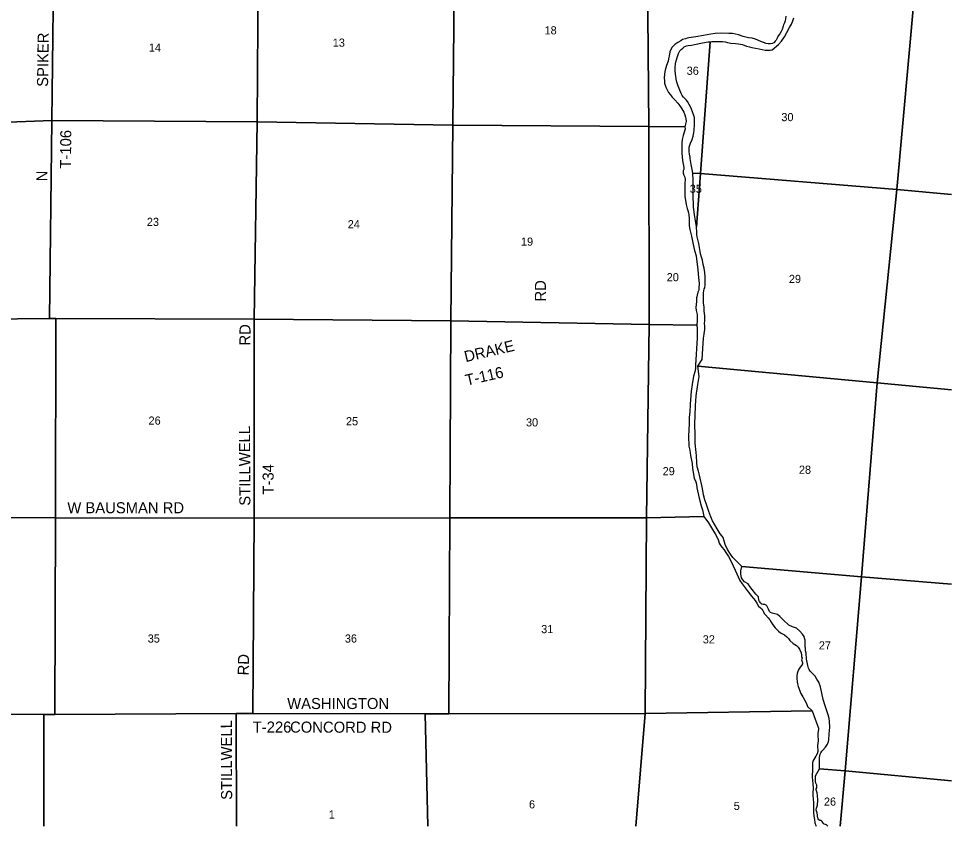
# Model space of a CAD drawing. Extents: x -87 to 2145, y -2128 to 440.
# Drawn here: x 204.7 to 331.2, y -2126.1 to -2016.6 of the extents above; entities that cross this region are included whole.
import ezdxf

# ---------------------------------------------------------------- set-up
doc = ezdxf.new("R2010")
doc.units = 0
for name, color, linetype in [('GM_X_Section', 7, 'Continuous'), ('GM_X_Section_Text', 7, 'Continuous'), ('GM_X_Township_Road_Text', 7, 'Continuous')]:
    doc.layers.add(name, color=color, linetype=linetype)

msp = doc.modelspace()

# ---------------------------------------------------------------- linework, layer by layer
at = {"layer": 'GM_X_Section'}
for points in [[(183.38, -2004.69), (209.52, -2003.86), (209.22, -2030.41), (194.99, -2030.93), (183.1, -2030.7)], [(237.27, -2004.15), (237.06, -2030.59), (209.22, -2030.41), (209.52, -2003.86)], [(237.27, -2004.15), (263.85, -2004.34), (263.59, -2031.02), (237.06, -2030.59)], [(263.85, -2004.34), (288.73, -2004.69), (288.94, -2004.98), (289.06, -2005.09), (289.25, -2005.27), (289.56, -2005.57), (289.96, -2005.92), (290.16, -2031.2), (263.59, -2031.02)], [(298.51, -2019.76), (297.19, -2037.61), (296.15, -2037.56), (296.07, -2037.07), (295.96, -2036.62), (295.94, -2036.39), (295.79, -2035.58), (295.78, -2035.39), (295.69, -2034.99), (295.65, -2034.6), (295.64, -2034.3), (295.66, -2034.04), (295.72, -2033.77), (295.82, -2033.48), (296.06, -2032.98), (296.21, -2032.55), (296.3, -2032.06), (296.33, -2031.74), (296.38, -2030.98), (296.39, -2030.45), (296.36, -2030.03), (296.29, -2029.72), (296.16, -2029.39), (295.9, -2028.73), (295.65, -2028.26), (295.44, -2027.85), (295.24, -2027.59), (294.9, -2027.26), (294.7, -2027.01), (294.57, -2026.73), (294.28, -2026.07), (294.11, -2025.62), (293.99, -2025.19), (293.89, -2024.78), (293.85, -2024.37), (293.78, -2024.18), (293.75, -2023.59), (293.75, -2023.16), (293.78, -2022.71), (293.87, -2022.33), (294.06, -2021.74), (294.1, -2021.6), (294.22, -2021.33), (294.39, -2020.96), (294.56, -2020.78), (294.79, -2020.58), (294.99, -2020.42), (295.29, -2020.28), (295.5, -2020.24), (295.98, -2020.18), (296.38, -2020.11), (297.44, -2019.89), (298.21, -2019.76)], [(183.1, -2030.7), (194.99, -2030.93), (209.22, -2030.41), (208.91, -2057.25), (182.93, -2057.54)], [(209.22, -2030.41), (237.06, -2030.59), (236.68, -2057.34), (209.76, -2057.25), (208.91, -2057.25)], [(237.06, -2030.59), (263.59, -2031.02), (263.35, -2057.57), (236.68, -2057.34)], [(263.59, -2031.02), (290.16, -2031.2), (290.23, -2058.07), (263.35, -2057.57)], [(290.16, -2031.2), (295.07, -2031.26), (295.09, -2031.54), (295.03, -2031.86), (294.85, -2032.44), (294.7, -2032.97), (294.64, -2033.5), (294.66, -2034.08), (294.67, -2034.8), (294.71, -2035.38), (294.74, -2035.8), (294.8, -2036.1), (294.9, -2036.5), (294.93, -2036.81), (294.92, -2037.04), (294.85, -2037.24), (294.83, -2037.37), (294.84, -2037.54), (294.93, -2037.83), (295.07, -2038.11), (295.1, -2038.39), (295.07, -2038.93), (295.08, -2039.81), (295.06, -2040.34), (295.05, -2040.71), (295.15, -2041.23), (295.24, -2041.82), (295.36, -2042.36), (295.47, -2042.63), (295.57, -2042.95), (295.62, -2043.2), (295.63, -2043.7), (295.63, -2044.12), (295.65, -2044.69), (295.75, -2045.18), (295.96, -2046.09), (296.05, -2046.54), (296.17, -2047.23), (296.39, -2048.03), (296.59, -2048.75), (296.65, -2049.22), (296.74, -2049.91), (296.81, -2050.68), (296.92, -2051.7), (296.99, -2052.51), (296.98, -2053.12), (296.94, -2053.4), (296.83, -2053.7), (296.71, -2054.11), (296.67, -2054.32), (296.66, -2054.48), (296.62, -2054.94), (296.57, -2055.76), (296.6, -2056.16), (296.71, -2056.71), (296.72, -2057.51), (296.7, -2058.18), (290.23, -2058.07)], [(297.19, -2037.61), (296.66, -2044.81), (296.43, -2043.47), (296.25, -2042.17), (296.2, -2040.38), (296.2, -2038.51), (296.15, -2037.56)], [(297.19, -2037.61), (323.79, -2039.77), (321.15, -2065.99), (296.8, -2063.72), (297.43, -2062.83), (297.61, -2059.88), (297.61, -2059.88), (297.64, -2059.69), (297.69, -2059.34), (297.77, -2058.74), (297.76, -2058.34), (297.74, -2057.91), (297.75, -2057.64), (297.76, -2056.92), (297.7, -2056.25), (297.68, -2055.71), (297.61, -2055.12), (297.59, -2054.83), (297.57, -2054.67), (297.57, -2054.4), (297.6, -2053.77), (297.69, -2053.26), (297.76, -2053.11), (297.81, -2052.72), (297.82, -2052.25), (297.82, -2051.6), (297.77, -2051.04), (297.67, -2050.42), (297.56, -2049.92), (297.44, -2049.37), (297.31, -2048.93), (297.18, -2048.5), (297.14, -2048.18), (297.04, -2047.65), (296.95, -2047.1), (296.72, -2046.18), (296.69, -2045.86), (296.67, -2045.54), (296.66, -2044.81)], [(208.91, -2057.25), (209.76, -2057.25), (209.72, -2084.32), (182.37, -2084.18), (182.93, -2057.54)], [(209.76, -2057.25), (236.68, -2057.34), (236.68, -2084.35), (209.72, -2084.32)], [(236.68, -2057.34), (263.35, -2057.57), (263.19, -2084.29), (236.68, -2084.35)], [(263.35, -2057.57), (290.23, -2058.07), (289.88, -2084.28), (263.19, -2084.29)], [(290.23, -2058.07), (296.7, -2058.18), (296.71, -2058.65), (296.75, -2059.86), (296.75, -2059.87), (296.5, -2063.6), (296.5, -2063.96), (296.44, -2064.34), (296.23, -2065.09), (296.04, -2066.2), (295.92, -2067.13), (295.78, -2068.86), (295.73, -2069.97), (295.64, -2070.64), (295.63, -2071.51), (295.57, -2073.21), (295.6, -2074.59), (295.72, -2075.13), (295.82, -2075.86), (296.04, -2076.95), (296.12, -2077.63), (296.33, -2078.91), (296.54, -2079.43), (296.64, -2079.74), (296.69, -2080.24), (296.99, -2081.65), (297.26, -2082.66), (297.45, -2083.22), (297.64, -2084.12), (289.88, -2084.28)], [(321.15, -2065.99), (319.03, -2092.32), (302.81, -2090.91), (301.57, -2089.7), (301.23, -2089.21), (300.84, -2088.61), (300.52, -2087.92), (300.25, -2086.97), (300.12, -2086.78), (299.84, -2086.47), (299.43, -2085.79), (298.81, -2084.69), (298.57, -2084.16), (298.3, -2083.44), (297.99, -2082.5), (297.78, -2081.84), (297.61, -2081.17), (297.45, -2080.31), (297.06, -2078.53), (296.93, -2077.96), (296.73, -2077.38), (296.68, -2076.81), (296.64, -2075.88), (296.61, -2075.44), (296.46, -2074.19), (296.46, -2073.14), (296.41, -2071.53), (296.48, -2070.4), (296.52, -2069.09), (296.55, -2068.39), (296.6, -2067.84), (296.64, -2067.36), (296.68, -2067.16), (296.8, -2066.22), (297.01, -2065.12), (296.8, -2063.72)], [(182.37, -2084.18), (209.72, -2084.32), (209.65, -2110.99), (208.16, -2110.98), (182.98, -2110.89)], [(289.88, -2084.28), (297.64, -2084.12), (298.26, -2084.96), (298.52, -2085.42), (298.83, -2085.86), (299.18, -2086.49), (299.57, -2087.25), (299.72, -2087.72), (299.85, -2087.95), (300.07, -2088.27), (300.41, -2088.64), (300.51, -2088.87), (300.97, -2089.55), (301.19, -2089.93), (301.62, -2090.81), (301.89, -2091.38), (302.54, -2092.82), (302.84, -2093.27), (303.65, -2094.34), (304.12, -2094.92), (304.38, -2095.24), (304.59, -2095.51), (304.82, -2095.88), (305.06, -2096.26), (305.32, -2096.5), (305.52, -2096.68), (305.62, -2096.85), (305.72, -2097.06), (305.8, -2097.26), (305.98, -2097.46), (306.36, -2097.86), (306.57, -2098.12), (306.75, -2098.45), (307.01, -2098.83), (307.32, -2099.2), (307.74, -2099.65), (308.04, -2099.91), (308.56, -2100.17), (308.91, -2100.44), (309.1, -2100.67), (309.31, -2100.95), (309.76, -2101.34), (310.19, -2101.6), (310.44, -2101.84), (310.62, -2102.12), (310.83, -2102.63), (310.87, -2102.93), (310.87, -2103.1), (310.95, -2103.35), (310.9, -2103.56), (310.92, -2103.7), (311.03, -2103.9), (311.03, -2104.08), (310.88, -2104.33), (310.69, -2104.54), (310.52, -2104.81), (310.39, -2105.13), (310.3, -2105.4), (310.26, -2105.74), (310.24, -2106.04), (310.29, -2106.59), (310.32, -2106.81), (310.44, -2107.18), (310.8, -2108.11), (311.06, -2108.59), (311.45, -2109.3), (311.59, -2109.61), (311.68, -2109.87), (312.32, -2110.49), (289.67, -2110.84)], [(209.72, -2084.32), (236.68, -2084.35), (236.49, -2110.84), (234.2, -2110.84), (209.65, -2110.99)], [(236.68, -2084.35), (263.19, -2084.29), (263.06, -2110.89), (259.85, -2110.87), (236.49, -2110.84)], [(289.88, -2084.28), (289.67, -2110.84), (263.06, -2110.89), (263.19, -2084.29)], [(319.03, -2092.32), (316.78, -2118.62), (313.31, -2118.33), (313.3, -2117.24), (313.33, -2116.79), (313.41, -2116.36), (313.48, -2116.19), (313.64, -2115.96), (313.78, -2115.83), (314.14, -2115.4), (314.41, -2114.98), (314.53, -2114.65), (314.58, -2114.4), (314.62, -2113.6), (314.71, -2112.69), (314.68, -2111.93), (314.63, -2111.52), (314.51, -2111), (314.11, -2109.79), (313.8, -2108.94), (313.62, -2108.07), (313.44, -2107.21), (313.23, -2106.59), (312.98, -2106.16), (312.72, -2105.79), (312.07, -2105.08), (311.91, -2104.89), (311.84, -2104.68), (311.76, -2104.31), (311.57, -2103.46), (311.5, -2102.65), (311.41, -2102.35), (311.38, -2101.4), (311.38, -2100.9), (311.29, -2100.63), (311.22, -2100.41), (311.03, -2100.06), (310.64, -2099.66), (310.21, -2099.28), (309.64, -2099.07), (309.17, -2098.87), (308.38, -2098.15), (307.95, -2097.66), (307.61, -2097.43), (306.92, -2097.25), (306.68, -2097.13), (306.52, -2096.99), (306.41, -2096.68), (306.16, -2096.25), (306.07, -2096.13), (305.91, -2096.06), (305.66, -2096.07), (305.49, -2096.01), (305.35, -2095.88), (305.17, -2095.65), (305.08, -2095.46), (305.03, -2095), (304.7, -2094.63), (304.18, -2094.01), (303.89, -2093.59), (303.67, -2093.27), (303.16, -2092.97), (302.93, -2092.73), (302.74, -2092.42), (302.67, -2091.92), (302.66, -2091.47), (302.81, -2090.91)]]:
    msp.add_lwpolyline(points, close=True, dxfattribs=at)
for points in [[(308.77, -2016.26), (308.73, -2016.6), (308.65, -2016.91), (308.57, -2017.16), (308.44, -2017.44), (308.41, -2017.6), (308.26, -2018.07), (308.13, -2018.35), (307.95, -2018.65), (307.77, -2018.86), (307.71, -2018.93), (307.58, -2019.25), (307.44, -2019.53), (307.32, -2019.67), (307.13, -2019.86), (306.9, -2019.96), (306.66, -2020.01), (306.38, -2020.01), (306.09, -2019.95), (305.37, -2019.68), (304.63, -2019.39), (304.17, -2019.24), (303.7, -2019.18), (303.32, -2019.1), (302.97, -2019.01), (302.33, -2018.81), (301.51, -2018.63), (301.02, -2018.6), (300, -2018.58), (299.18, -2018.62), (298.58, -2018.69), (297.59, -2018.87), (296.54, -2019.06), (295.62, -2019.21), (295.39, -2019.26), (295.13, -2019.35), (294.75, -2019.44), (294.5, -2019.59), (294.13, -2019.83), (293.69, -2020.1), (293.51, -2020.26), (293.36, -2020.46), (293.18, -2020.76), (293.04, -2021.09), (292.92, -2021.7), (292.86, -2022.05), (292.8, -2022.37), (292.57, -2022.95), (292.38, -2023.57), (292.31, -2024.06), (292.27, -2024.66), (292.3, -2024.99), (292.31, -2025.36), (292.47, -2025.89), (292.85, -2026.59), (293.05, -2026.88), (293.34, -2027.23), (293.7, -2027.6), (294.1, -2028.04), (294.37, -2028.41), (294.66, -2028.84), (294.92, -2029.29), (295.07, -2029.64), (295.17, -2029.95), (295.2, -2030.15), (295.25, -2030.54), (295.07, -2031.26), (290.16, -2031.2), (289.96, -2005.92)], [(326.21, -2013.25), (323.79, -2039.77), (297.19, -2037.61), (298.51, -2019.76), (298.73, -2019.7), (299.52, -2019.71), (300.16, -2019.7), (300.54, -2019.75), (300.86, -2019.83), (301.28, -2019.92), (301.93, -2019.96), (302.35, -2020.01), (302.88, -2020.12), (303.43, -2020.32), (303.82, -2020.43), (304.16, -2020.52), (304.63, -2020.61), (305.15, -2020.7), (305.96, -2020.86), (306.22, -2020.88), (306.63, -2020.87), (306.88, -2020.82), (307.74, -2020.11), (308.17, -2019.65), (308.59, -2019.07), (308.91, -2018.49), (309.27, -2017.78), (309.51, -2017.32), (309.71, -2016.87), (309.84, -2016.47)], [(331.2, -2040.46), (323.79, -2039.77), (326.21, -2013.25), (331.2, -2013.72)], [(331.2, -2066.93), (321.15, -2065.99), (323.79, -2039.77), (331.2, -2040.46)], [(331.2, -2093.31), (319.03, -2092.32), (321.15, -2065.99), (331.2, -2066.93)], [(331.2, -2119.97), (316.78, -2118.62), (319.03, -2092.32), (331.2, -2093.31)], [(288.41, -2126.14), (289.67, -2110.84), (312.32, -2110.49), (312.74, -2111.62), (312.87, -2111.95), (313.05, -2112.46), (313.17, -2112.84), (313.17, -2113.08), (313.14, -2113.21), (313.1, -2113.6), (313.09, -2113.97), (313.14, -2114.34), (313.13, -2114.53), (313.08, -2114.87), (313.07, -2115.16), (313.08, -2115.98), (313.02, -2116.29), (312.84, -2116.64), (312.67, -2116.84), (312.53, -2117.07), (312.4, -2117.32), (312.36, -2117.52), (312.36, -2118.13), (312.38, -2118.65), (312.33, -2119.14), (312.31, -2119.43), (312.36, -2119.95), (312.42, -2120.32), (312.45, -2121), (312.41, -2121.61), (312.43, -2121.88), (312.48, -2122.51), (312.51, -2122.85), (312.51, -2123.49), (312.52, -2123.64), (312.49, -2123.88), (312.5, -2124.04), (312.5, -2124.26), (312.57, -2124.74), (312.62, -2125.23), (312.7, -2125.65), (312.84, -2126.04), (312.89, -2126.14)], [(182.14, -2126.14), (182.14, -2110.9), (182.98, -2110.89), (208.16, -2110.98), (208.12, -2126.14)], [(208.12, -2126.14), (208.16, -2110.98), (209.65, -2110.99), (234.2, -2110.84), (234.26, -2126.14)], [(234.26, -2126.14), (234.2, -2110.84), (236.49, -2110.84), (259.85, -2110.87), (260.21, -2126.14)], [(260.21, -2126.14), (259.85, -2110.87), (263.06, -2110.89), (289.67, -2110.84), (288.41, -2126.14)], [(314.45, -2126.14), (314.43, -2126.12), (314.27, -2125.94), (314.12, -2125.91), (313.94, -2125.85), (313.82, -2125.73), (313.66, -2125.47), (313.55, -2125.37), (313.38, -2125.34), (313.24, -2125.27), (313.14, -2125.11), (313.08, -2124.96), (313.06, -2124.85), (313.04, -2124.62), (312.99, -2124.3), (312.9, -2124.1), (312.88, -2123.88), (312.93, -2123.68), (313.05, -2123.28), (313.09, -2122.61), (313.06, -2121.98), (313.02, -2121.59), (312.92, -2121.33), (312.87, -2121.18), (312.88, -2121.06), (312.97, -2120.91), (312.97, -2120.69), (312.94, -2120.58), (312.82, -2120.27), (312.76, -2120.07), (312.76, -2119.8), (312.77, -2119.61), (312.79, -2119.28), (313.31, -2118.33), (316.78, -2118.62), (316.14, -2126.14)], [(316.14, -2126.14), (316.78, -2118.62), (331.2, -2119.97)]]:
    msp.add_lwpolyline(points, dxfattribs=at)

# ---------------------------------------------------------------- texts
at = {"layer": 'GM_X_Section_Text'}
for s, height, p in [('18', 1.105, (276.04, -2018.73)), ('13', 1.105, (247.32, -2020.4)), ('14', 1.105, (222.38, -2021.07)), ('36', 1.105, (295.31, -2024.21)), ('30', 1.105, (308.15, -2030.5)), ('35', 1.105, (295.73, -2040.22)), ('23', 1.105, (222.11, -2044.71)), ('24', 1.105, (249.35, -2045.03)), ('19', 1.105, (272.84, -2047.39)), ('20', 1.105, (292.6, -2052.21)), ('29', 1.105, (309.17, -2052.45)), ('26', 1.105, (222.34, -2071.66)), ('25', 1.105, (249.11, -2071.75)), ('30', 1.105, (273.52, -2071.9)), ('29', 1.105, (292.05, -2078.52)), ('28', 1.105, (310.53, -2078.33)), ('31', 1.105, (275.58, -2099.94)), ('35', 1.105, (222.23, -2101.22)), ('36', 1.105, (248.96, -2101.22)), ('32', 1.105, (297.49, -2101.33)), ('27', 1.105, (313.23, -2102.15)), ('26', 1.105, (313.92, -2123.34)), ('6', 1.1, (273.93, -2123.71)), ('5', 1.1, (301.69, -2123.92)), ('1', 1.1, (246.78, -2125.08))]:
    msp.add_text(s, height=height, rotation=0, dxfattribs=at).set_placement(p)
at = {"layer": 'GM_X_Township_Road_Text'}
for s, rotation, p in [('SPIKER', 89.2248, (208.71, -2025.85)), ('T-106', 89.4388, (211.82, -2036.94)), ('N', 90, (208.63, -2038.66)), ('RD', 90, (276.23, -2054.96)), ('RD', 89.5063, (236.15, -2060.94)), ('DRAKE', 13.127, (265.34, -2063.19)), ('T-116', 12.8893, (265.48, -2066.39)), ('STILLWELL', 90.2504, (236.15, -2082.65)), ('T-34', 90.3557, (239.32, -2081.13)), ('W BAUSMAN RD', 0, (211.33, -2083.68)), ('RD', 89.0249, (235.93, -2105.68)), ('WASHINGTON', 0, (241.14, -2110.23)), ('STILLWELL', 90.2488, (233.68, -2122.55)), ('T-226', 0, (236.47, -2113.43)), ('CONCORD RD', 359.8946, (241.53, -2113.43))]:
    msp.add_text(s, height=1.5, rotation=rotation, dxfattribs=at).set_placement(p)

doc.saveas('drawing.dxf')
